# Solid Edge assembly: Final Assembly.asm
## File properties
Author: Chalangana Oshan
Template: iso metric assembly.asm
Last saved by: Nimesh.N
Revision: 206
Application: Solid Edge
Username: Nimesh.N
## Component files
GearB.par
AST_Bearings_NU2314_E.par
lever__top.par
circlip-72-bs-3673.par
GearC.par
circlip-70-bs-3673.par
GearD.par
GearE.par
Bottom_Housing_Final.par
Input shaft.par
GearI.par
AST_Bearings_NUP213_E.par
Layshaft.par
bearing_nu_213_ecp_2.par
gearshift_with 3 & 4 gears.par
outer_shaft_1,2(red).par
outer_shaft_3,4(blue).par
B lever shaft.par
A lever shaft.par
Top_Housing_Final.par
housing top top part.par
Idler Shaft.par
GearA New.par
power shaft final final.par
81213.par
M20_nut.par
circlip-68-bs-3673.par
81113.par
GearF new.par
GearG new.par
lever_bottom.par
GearH new.par
circlip-65-bs-3673.par
power shaft key.par
Bevel Gear_1.par
Layshaft Key.par
circlip-55-bs-3673.par
M14_bolt.par
M14_nut.par
1224384.par
M20_bolt.par
gearshift_with 1 & 2 gears.par
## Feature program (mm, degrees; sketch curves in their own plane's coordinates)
assembly promote feature "unnamed AssemblyPromoteFeature 1"
sketch for "unnamed Cutout 1" plane through (130.0006, -284.6194, 10) normal (0, 0, 1) x-axis (1, 0, 0)
extrude "unnamed Cutout 1" cut
assembly promote feature "unnamed AssemblyPromoteFeature 2"
sketch for "unnamed Cutout 2" plane through (829.9995, 609.7238, 10) normal (0, 0, 1) x-axis (1, 0, 0)
extrude "unnamed Cutout 2" cut
assembly promote feature "unnamed AssemblyPromoteFeature 3"
sketch for "unnamed Cutout 3" plane through (97.6614, 454.1312, 10) normal (0, 0, 1) x-axis (1, 0, 0)
  circle centre (-47.6614, 15.8688) radius 10
extrude "unnamed Cutout 3" cut
pattern "unnamed Pattern 1" of "unnamed Cutout 1"
extrude "unnamed Cutout 4" cut
pattern "unnamed Pattern 2" of "unnamed Cutout 3"
extrude "unnamed Cutout 5" cut
assembly promote feature "unnamed AssemblyPromoteFeature 4"
sketch for "unnamed Cutout 6" plane through (864.1204, 5.9224, 10) normal (0, 0, 1) x-axis (1, 0, 0)
  circle centre (-396.1204, -195.9224) radius 10
extrude "unnamed Cutout 6" cut
pattern "unnamed Pattern 3" of "unnamed Cutout 6"
extrude "unnamed Cutout 7" cut
extrude "unnamed Cutout 8" cut
extrude "unnamed Cutout 9" cut
extrude "unnamed Cutout 10" cut
assembly promote feature "unnamed AssemblyPromoteFeature 5"
sketch for "unnamed Cutout 11" plane through (105.8755, -35.5245, 10) normal (0, 0, 1) x-axis (1, 0, 0)
  circle centre (-140.8755, 193.1519) radius 10
extrude "unnamed Cutout 11" cut
assembly promote feature "unnamed AssemblyPromoteFeature 6"
sketch for "unnamed Cutout 12" plane through (105.8755, -35.5245, 10) normal (0, 0, 1) x-axis (1, 0, 0)
  circle centre (-140.8755, -161.9755) radius 10
extrude "unnamed Cutout 12" cut
assembly promote feature "unnamed AssemblyPromoteFeature 7"
sketch for "unnamed Cutout 13" plane through (864.1204, 5.9224, 10) normal (0, 0, 1) x-axis (1, 0, 0)
  circle centre (570.8796, -154.9224) radius 10
extrude "unnamed Cutout 13" cut
assembly promote feature "unnamed AssemblyPromoteFeature 8"
sketch for "unnamed Cutout 14" plane through (855.6239, 508.0704, 10) normal (0, 0, 1) x-axis (1, 0, 0)
  circle centre (579.3761, 16.9296) radius 10
extrude "unnamed Cutout 14" cut
assembly promote feature "unnamed AssemblyPromoteFeature 9"
sketch for "unnamed Cutout 15" plane through (864.1204, 5.9224, 10) normal (0, 0, 1) x-axis (1, 0, 0)
  circle centre (570.8796, 144.0779) radius 10
extrude "unnamed Cutout 15" cut
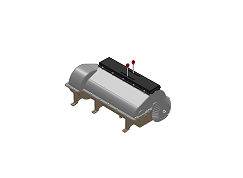
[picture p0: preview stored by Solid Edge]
